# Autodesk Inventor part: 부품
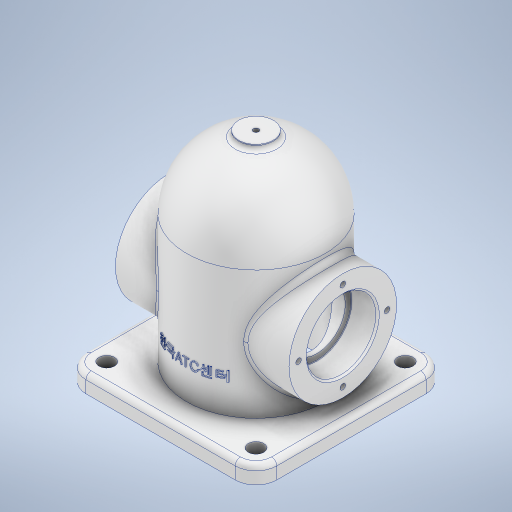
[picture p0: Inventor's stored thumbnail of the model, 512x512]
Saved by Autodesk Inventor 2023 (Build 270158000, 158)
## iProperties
Created: 2025-04
Part Number: 부품
Material: 알루미늄 6061
Document SubType Name: Modeling
Designer: ADMIN_PC
Density: 2.7 g/cm^3
Appearance: 알루미늄 - 평지
Mass: 862.141 g
Surface Area: 800.899 cm^2
Volume: 319.311 cm^3
Author: ADMIN_PC
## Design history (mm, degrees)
sketch "스케치1"
  geometry: L1 (-57.966, 0)-(9.806, 0) reference; L2 (-40, -34.5)-(0, -34.5); L3 (-40, 39.5)-(-40, -34.5); L4 (0, -58.957)-(0, 112.241) reference; L5 (0, 79.5)-(0, -34.5); A1 r 39.378 centre (0, 39.5) between (-0.124, 0.122) and (0.124, 0.122); A2 r 40 centre (0, 39.5) between (0, 79.5) and (-40, 39.5); 1 further point
  constraints: 6 end point, 4 point on circle, 2 centre point, 2 point on line, 1 collinear, 1 horizontal, 1 perpendicular
  dimensions: "d1" = 40 radius of A2; "d3" = 114 distance of L2.end L5.start
revolve "회전1" sketch "스케치1" stored, may be unused: angle "d4" = 90 deg
sketch "스케치2"
  geometry: L1 (-55, -55)-(55, -55); L2 (55, -55)-(55, 55); L3 (55, 55)-(-55, 55); L4 (-55, 55)-(-55, -55); L5 (-55, -55)-(55, 55); L6 (55, -55)-(-55, 55); 1 further point
  constraints: 12 end point, 2 midpoint, 2 parallel, 1 horizontal, 1 perpendicular
  dimensions: "d5" = 110 distance of L3.end L2.end; "d6" = 110 distance of L1.end L2.end
extrude "돌출1" join sketch "스케치2" distance "d7" = 10; taper "d8" = 0 deg
node "작업 평면1"
sketch "스케치4"
  geometry: L1 (-44.5, -55)-(-44.5, 55) reference; L2 (-60.3, 0)-(50.3, 0) reference; C1 r 31 at (3.5, 0); 1 further point
  constraints: 1 centre point, 1 point on line
  dimensions: "d10" = 62 diameter of C1; "d11" = 48 distance from line of L1 C1.centre
extrude "돌출2" join sketch "스케치4" stored distance "d12" = 10; taper "d13" = 0 deg
fillet "모깎기1" dims "d14" = 12
sketch "스케치5"
  geometry: C1 r 4.5 at (-43, -43); C2 r 4.5 at (-43, 43); C3 r 4.5 at (43, 43); C4 r 4.5 at (43, -43); A1 r 12 centre (-43, -43) between (-55, -43) and (-43, -55) reference; A2 r 12 centre (-43, 43) between (-43, 55) and (-55, 43) reference; A3 r 12 centre (43, 43) between (55, 43) and (43, 55) reference; A4 r 12 centre (43, -43) between (43, -55) and (55, -43) reference; 1 further point
  constraints: 4 centre point, 4 coincident
  dimensions: "d15" = 9 diameter of C1; "d16" = 9 diameter of C2; "d17" = 9 diameter of C3; "d18" = 9 diameter of C4
extrude "돌출3" cut sketch "스케치5" extent not by distance; stored distance "d19" = 0; taper "d20" = 0 deg
sketch "스케치6" dims "d21" = 51
  geometry: C1 r 31 at (0, 0) reference; 3 further points
  constraints: 1 coincident, 1 vertical alignment, 2 other
hole "구멍1" sketch "스케치6" at (0, 25.5) diameter "d22" = 3.242; stored, may be unused: countersink angle "d26" = 90 deg, drill point angle "d28" = 118 deg; dims "d23" = 8, "d24" = 4, "d25" = 2, "d27" = 10
sketch "스케치7"
  geometry: C1 r 31 at (0, 0) reference; C2 r 20 at (0, 0); 1 further point
  constraints: 1 centre point, 1 coincident
  dimensions: "d32" = 40 diameter of C2
extrude "돌출4" cut sketch "스케치7" distance "d33" = 15; taper "d34" = 0 deg
sketch "스케치8"
  geometry: C1 r 20 at (0, 0) reference; C2 r 16.5 at (0, 0); 1 further point
  constraints: 1 centre point, 1 coincident
  dimensions: "d35" = 33 diameter of C2
extrude "돌출5" cut sketch "스케치8" extent not by distance; stored distance "d36" = 0; taper "d37" = 0 deg
node "작업 평면2"
sketch "스케치11"
  geometry: C1 r 10 at (0, 0); 1 further point
  constraints: 1 centre point, 1 coincident
  dimensions: "d39" = 20 diameter of C1
extrude "돌출6" join sketch "스케치11" stored distance "d40" = 10; taper "d41" = 0 deg
sketch "스케치13"
  geometry: L1 (-40, -34.5)-(-40, 39.5) reference; L2 (40, -34.5)-(40, 39.5) reference; L3 (-32, 39.5)-(-32, -44.5); L4 (-43, -44.5)-(43, -44.5) reference; L5 (0, 71.5)-(0, -44.5); L6 (-32, -44.5)-(0, -44.5); L7 (0, -69.3)-(0, 104.3) reference; A1 r 40 centre (0, 39.5) between (40, 39.5) and (-40, 39.5) reference; A2 r 32 centre (0, 39.5) between (0, 71.5) and (-32, 39.5); 1 further point
  constraints: 6 end point, 2 point on circle, 2 point on line, 1 centre point, 1 collinear, 1 midpoint, 1 vertical
  dimensions: "d42" = 8 radial gap between concentric circles of A1 A2; "d44" = 32 distance between parallel lines of L5 L3
revolve "회전2" sketch "스케치13" stored, may be unused: angle "d45" = 90 deg
sketch "스케치15"
  geometry: C1 r 32 at (0, 0) reference; 2 further points
  constraints: 1 coincident
hole "구멍2" sketch "스케치15" at (0, 0) diameter "d46" = 3.242; stored, may be unused: countersink angle "d50" = 90 deg, drill point angle "d52" = 118 deg; dims "d47" = 40, "d48" = 4, "d49" = 2, "d51" = 50
chamfer "모따기1" distance "d53" = 1; stored, may be unused: second distance "d54" = 2, angle "d55" = 45 deg
fillet "모깎기2" dims "d56" = 0.3
fillet "모깎기3" dims "d57" = 3
node "작업 평면3"
sketch "스케치16"
  geometry: L1 (43, -44.5)-(-43, -44.5) reference; L2 (0, -69.6)-(0, 106.1) reference; 2 further points
  constraints: 1 point on line, 1 other
  dimensions: "d59" = 30 distance from line of L1 point (0, -14.5)
feature "엠보싱1" sketch "스케치16" dims "d60" = 0.5, "d61" = 0
node "솔리드1"
mirror "미러1"
pattern_circular "원형 패턴1" dims angle "d30" = 360 deg
mirror "미러2"
mirror "미러3"
feature "A9D066F2-1C7D-4E18-AEED-F7BC21143FA4" dims "d22" = 3.242, "d23" = 8, "d24" = 4, "d25" = 2, "d26" = 90 deg, "d27" = 10, "d28" = 118 deg
other parameters: "d38" = 81, "d58" = 74
